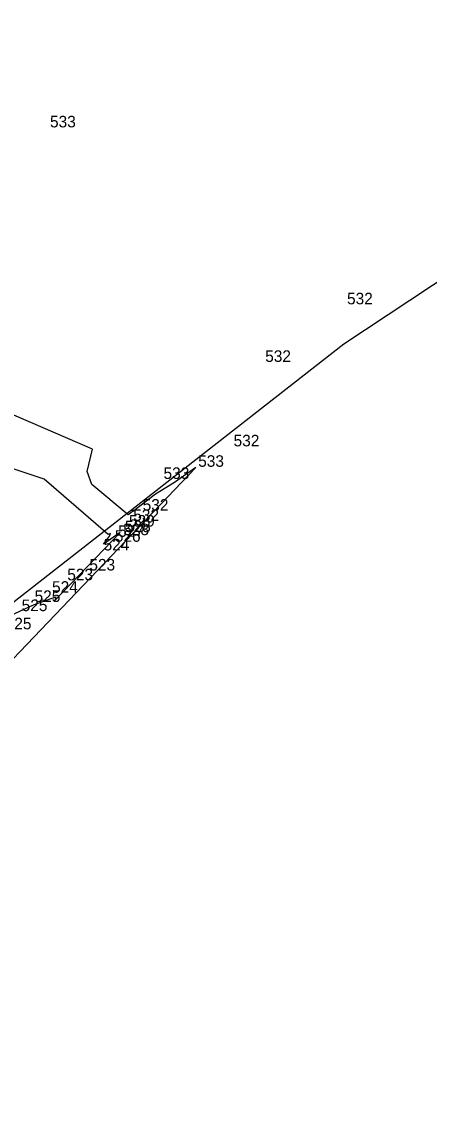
# Model space of a CAD drawing. Extents: x 1787461 to 1970323, y 938412 to 1118748.
# Drawn here: x 1967834 to 1967904.5, y 1117378.7 to 1117568.5 of the extents above; entities that cross this region are included whole.
import ezdxf

# ---------------------------------------------------------------- set-up
doc = ezdxf.new("R2010")
doc.units = 0
doc.layers.add('Default', color=7, linetype='Continuous')
doc.layers.add('HHA ADDITIONAL XSs', color=7, linetype='Continuous')

msp = doc.modelspace()

# ---------------------------------------------------------------- linework, layer by layer
at = {"layer": 'Default'}
for points in [[(1967864.09, 1117491.4), (1967860.39, 1117488.79), (1967857.14, 1117486.78), (1967853.13, 1117483.68), (1967853.29, 1117484.04), (1967852.82, 1117483.54), (1967852.36, 1117483.18), (1967846.09, 1117488.43), (1967845.27, 1117490.67), (1967846.19, 1117494.55), (1967828.68, 1117502.13), (1967821.49, 1117503.37), (1967805.34, 1117509.98), (1967800.65, 1117512.37), (1967795, 1117514.63), (1967789.01, 1117520.57), (1967781.48, 1117526.67), (1967771.5, 1117534.74), (1967762.73, 1117543.19), (1967757.96, 1117556.81), (1967755.44, 1117564.85), (1967761.67, 1117572.63)], [(1967864.09, 1117491.4), (1967860.39, 1117488.79), (1967857.14, 1117486.78), (1967853.13, 1117483.68), (1967853.29, 1117484.04), (1967852.82, 1117483.54), (1967852.36, 1117483.18), (1967846.09, 1117488.43), (1967845.27, 1117490.67), (1967846.19, 1117494.55), (1967828.68, 1117502.13), (1967821.49, 1117503.37), (1967805.34, 1117509.98), (1967800.65, 1117512.37), (1967795, 1117514.63), (1967789.01, 1117520.57), (1967781.48, 1117526.67), (1967771.5, 1117534.74), (1967762.73, 1117543.19), (1967757.96, 1117556.81), (1967755.44, 1117564.85), (1967761.67, 1117572.63)], [(1967864.09, 1117491.4), (1967860.39, 1117488.79), (1967857.14, 1117486.78), (1967853.13, 1117483.68), (1967853.29, 1117484.04), (1967852.82, 1117483.54), (1967852.36, 1117483.18), (1967846.09, 1117488.43), (1967845.27, 1117490.67), (1967846.19, 1117494.55), (1967828.68, 1117502.13), (1967821.49, 1117503.37), (1967805.34, 1117509.98), (1967800.65, 1117512.37), (1967795, 1117514.63), (1967789.01, 1117520.57), (1967781.48, 1117526.67), (1967771.5, 1117534.74), (1967762.73, 1117543.19), (1967757.96, 1117556.81), (1967755.44, 1117564.85), (1967761.67, 1117572.63)], [(1967864.09, 1117491.4), (1967860.39, 1117488.79), (1967857.14, 1117486.78), (1967853.13, 1117483.68), (1967853.29, 1117484.04), (1967852.82, 1117483.54), (1967852.36, 1117483.18), (1967846.09, 1117488.43), (1967845.27, 1117490.67), (1967846.19, 1117494.55), (1967828.68, 1117502.13), (1967821.49, 1117503.37), (1967805.34, 1117509.98), (1967800.65, 1117512.37), (1967795, 1117514.63), (1967789.01, 1117520.57), (1967781.48, 1117526.67), (1967771.5, 1117534.74), (1967762.73, 1117543.19), (1967757.96, 1117556.81), (1967755.44, 1117564.85), (1967761.67, 1117572.63)], [(1967864.09, 1117491.4), (1967860.39, 1117488.79), (1967857.14, 1117486.78), (1967853.13, 1117483.68), (1967853.29, 1117484.04), (1967852.82, 1117483.54), (1967852.36, 1117483.18), (1967846.09, 1117488.43), (1967845.27, 1117490.67), (1967846.19, 1117494.55), (1967828.68, 1117502.13), (1967821.49, 1117503.37), (1967805.34, 1117509.98), (1967800.65, 1117512.37), (1967795, 1117514.63), (1967789.01, 1117520.57), (1967781.48, 1117526.67), (1967771.5, 1117534.74), (1967762.73, 1117543.19), (1967757.96, 1117556.81), (1967755.44, 1117564.85), (1967761.67, 1117572.63)], [(1967864.09, 1117491.4), (1967860.39, 1117488.79), (1967857.14, 1117486.78), (1967853.13, 1117483.68), (1967853.29, 1117484.04), (1967852.82, 1117483.54), (1967852.36, 1117483.18), (1967846.09, 1117488.43), (1967845.27, 1117490.67), (1967846.19, 1117494.55), (1967828.68, 1117502.13), (1967821.49, 1117503.37), (1967805.34, 1117509.98), (1967800.65, 1117512.37), (1967795, 1117514.63), (1967789.01, 1117520.57), (1967781.48, 1117526.67), (1967771.5, 1117534.74), (1967762.73, 1117543.19), (1967757.96, 1117556.81), (1967755.44, 1117564.85), (1967761.67, 1117572.63)], [(1967864.09, 1117491.4), (1967860.39, 1117488.79), (1967857.14, 1117486.78), (1967853.13, 1117483.68), (1967853.29, 1117484.04), (1967852.82, 1117483.54), (1967852.36, 1117483.18), (1967846.09, 1117488.43), (1967845.27, 1117490.67), (1967846.19, 1117494.55), (1967828.68, 1117502.13), (1967821.49, 1117503.37), (1967805.34, 1117509.98), (1967800.65, 1117512.37), (1967795, 1117514.63), (1967789.01, 1117520.57), (1967781.48, 1117526.67), (1967771.5, 1117534.74), (1967762.73, 1117543.19), (1967757.96, 1117556.81), (1967755.44, 1117564.85), (1967761.67, 1117572.63)], [(1967760.21, 1117493.2), (1967772.53, 1117484.63), (1967775.68, 1117482.44), (1967779.55, 1117478.56), (1967788.15, 1117473.67), (1967796.17, 1117468.34), (1967802.58, 1117463.41), (1967815.73, 1117459.23), (1967820.53, 1117455.96), (1967821.67, 1117455.55), (1967821.73, 1117455.57), (1967821.73, 1117455.32), (1967823.12, 1117455.95), (1967821.79, 1117451.31), (1967823.86, 1117452.27), (1967825.53, 1117452.87), (1967825.06, 1117450.6), (1967864.09, 1117491.4)], [(1967760.21, 1117493.2), (1967772.53, 1117484.63), (1967775.68, 1117482.44), (1967779.55, 1117478.56), (1967788.15, 1117473.67), (1967796.17, 1117468.34), (1967802.58, 1117463.41), (1967815.73, 1117459.23), (1967820.53, 1117455.96), (1967821.67, 1117455.55), (1967821.73, 1117455.57), (1967821.73, 1117455.32), (1967823.12, 1117455.95), (1967821.79, 1117451.31), (1967823.86, 1117452.27), (1967825.53, 1117452.87), (1967825.06, 1117450.6), (1967864.09, 1117491.4)], [(1967760.21, 1117493.2), (1967772.53, 1117484.63), (1967775.68, 1117482.44), (1967779.55, 1117478.56), (1967788.15, 1117473.67), (1967796.17, 1117468.34), (1967802.58, 1117463.41), (1967815.73, 1117459.23), (1967820.53, 1117455.96), (1967821.67, 1117455.55), (1967821.73, 1117455.57), (1967821.73, 1117455.32), (1967823.12, 1117455.95), (1967821.79, 1117451.31), (1967823.86, 1117452.27), (1967825.53, 1117452.87), (1967825.06, 1117450.6), (1967864.09, 1117491.4)], [(1967760.21, 1117493.2), (1967772.53, 1117484.63), (1967775.68, 1117482.44), (1967779.55, 1117478.56), (1967788.15, 1117473.67), (1967796.17, 1117468.34), (1967802.58, 1117463.41), (1967815.73, 1117459.23), (1967820.53, 1117455.96), (1967821.67, 1117455.55), (1967821.73, 1117455.57), (1967821.73, 1117455.32), (1967823.12, 1117455.95), (1967821.79, 1117451.31), (1967823.86, 1117452.27), (1967825.53, 1117452.87), (1967825.06, 1117450.6), (1967864.09, 1117491.4)], [(1967760.21, 1117493.2), (1967772.53, 1117484.63), (1967775.68, 1117482.44), (1967779.55, 1117478.56), (1967788.15, 1117473.67), (1967796.17, 1117468.34), (1967802.58, 1117463.41), (1967815.73, 1117459.23), (1967820.53, 1117455.96), (1967821.67, 1117455.55), (1967821.73, 1117455.57), (1967821.73, 1117455.32), (1967823.12, 1117455.95), (1967821.79, 1117451.31), (1967823.86, 1117452.27), (1967825.53, 1117452.87), (1967825.06, 1117450.6), (1967864.09, 1117491.4)], [(1967760.21, 1117493.2), (1967772.53, 1117484.63), (1967775.68, 1117482.44), (1967779.55, 1117478.56), (1967788.15, 1117473.67), (1967796.17, 1117468.34), (1967802.58, 1117463.41), (1967815.73, 1117459.23), (1967820.53, 1117455.96), (1967821.67, 1117455.55), (1967821.73, 1117455.57), (1967821.73, 1117455.32), (1967823.12, 1117455.95), (1967821.79, 1117451.31), (1967823.86, 1117452.27), (1967825.53, 1117452.87), (1967825.06, 1117450.6), (1967864.09, 1117491.4)], [(1967825.06, 1117450.6), (1967864.09, 1117491.4)], [(1967831.24, 1117465.41), (1967835.98, 1117467.62), (1967839.84, 1117468.99), (1967839.7, 1117468.33), (1967850.98, 1117480.12), (1967848.11, 1117478.09), (1967849.16, 1117479.49), (1967849.31, 1117479.92), (1967848.91, 1117479.75), (1967837.86, 1117489.36), (1967832.47, 1117491.15)], [(1967831.24, 1117465.41), (1967835.98, 1117467.62), (1967839.84, 1117468.99), (1967839.7, 1117468.33), (1967850.98, 1117480.12), (1967848.11, 1117478.09), (1967849.16, 1117479.49), (1967849.31, 1117479.92), (1967848.91, 1117479.75), (1967837.86, 1117489.36), (1967832.47, 1117491.15)], [(1967831.24, 1117465.41), (1967835.98, 1117467.62), (1967839.84, 1117468.99), (1967839.7, 1117468.33), (1967850.98, 1117480.12), (1967848.11, 1117478.09), (1967849.16, 1117479.49), (1967849.31, 1117479.92), (1967848.91, 1117479.75), (1967837.86, 1117489.36), (1967832.47, 1117491.15)], [(1967831.24, 1117465.41), (1967835.98, 1117467.62), (1967839.84, 1117468.99), (1967839.7, 1117468.33), (1967850.98, 1117480.12), (1967848.11, 1117478.09), (1967849.16, 1117479.49), (1967849.31, 1117479.92), (1967848.91, 1117479.75), (1967837.86, 1117489.36), (1967832.47, 1117491.15)], [(1967831.24, 1117465.41), (1967835.98, 1117467.62), (1967839.84, 1117468.99), (1967839.7, 1117468.33), (1967850.98, 1117480.12), (1967848.11, 1117478.09), (1967849.16, 1117479.49), (1967849.31, 1117479.92), (1967848.91, 1117479.75), (1967837.86, 1117489.36), (1967832.47, 1117491.15)], [(1967831.24, 1117465.41), (1967835.98, 1117467.62), (1967839.84, 1117468.99), (1967839.7, 1117468.33), (1967850.98, 1117480.12), (1967848.11, 1117478.09), (1967849.16, 1117479.49), (1967849.31, 1117479.92), (1967848.91, 1117479.75), (1967837.86, 1117489.36), (1967832.47, 1117491.15)], [(1967831.24, 1117465.41), (1967835.98, 1117467.62), (1967839.84, 1117468.99), (1967839.7, 1117468.33), (1967850.98, 1117480.12), (1967848.11, 1117478.09), (1967849.16, 1117479.49), (1967849.31, 1117479.92), (1967848.91, 1117479.75), (1967837.86, 1117489.36), (1967832.47, 1117491.15)]]:
    msp.add_lwpolyline(points, dxfattribs=at)
at = {"layer": 'HHA ADDITIONAL XSs'}
msp.add_lwpolyline([(1969426.56, 1117649.38), (1968158.01, 1117641.45), (1967943.24, 1117548.13), (1967889.71, 1117512.72), (1967718.24, 1117378.75)], dxfattribs=at)

# ---------------------------------------------------------------- texts
at = {"layer": 'Default'}
for s, p in [('533', (1967838.85, 1117550.25)), ('532', (1967890.27, 1117519.62)), ('532', (1967876.1, 1117509.65)), ('532', (1967870.63, 1117495.03)), ('533', (1967864.5, 1117491.49)), ('533', (1967858.5, 1117489.39)), ('532', (1967854.89, 1117483.9)), ('529', (1967852.52, 1117481.14)), ('532', (1967853.26, 1117482.13)), ('526', (1967850.07, 1117478.51)), ('527', (1967850.65, 1117479.37)), ('528', (1967851.53, 1117479.66)), ('528', (1967851.82, 1117480.18)), ('524', (1967848.13, 1117477.01)), ('523', (1967845.66, 1117473.54)), ('523', (1967841.84, 1117471.84)), ('524', (1967839.2, 1117469.69)), ('525', (1967836.18, 1117468.1)), ('525', (1967833.94, 1117466.51)), ('525', (1967831.18, 1117463.36))]:
    msp.add_text(s, height=2, dxfattribs=at).set_placement(p)

doc.saveas('drawing.dxf')
